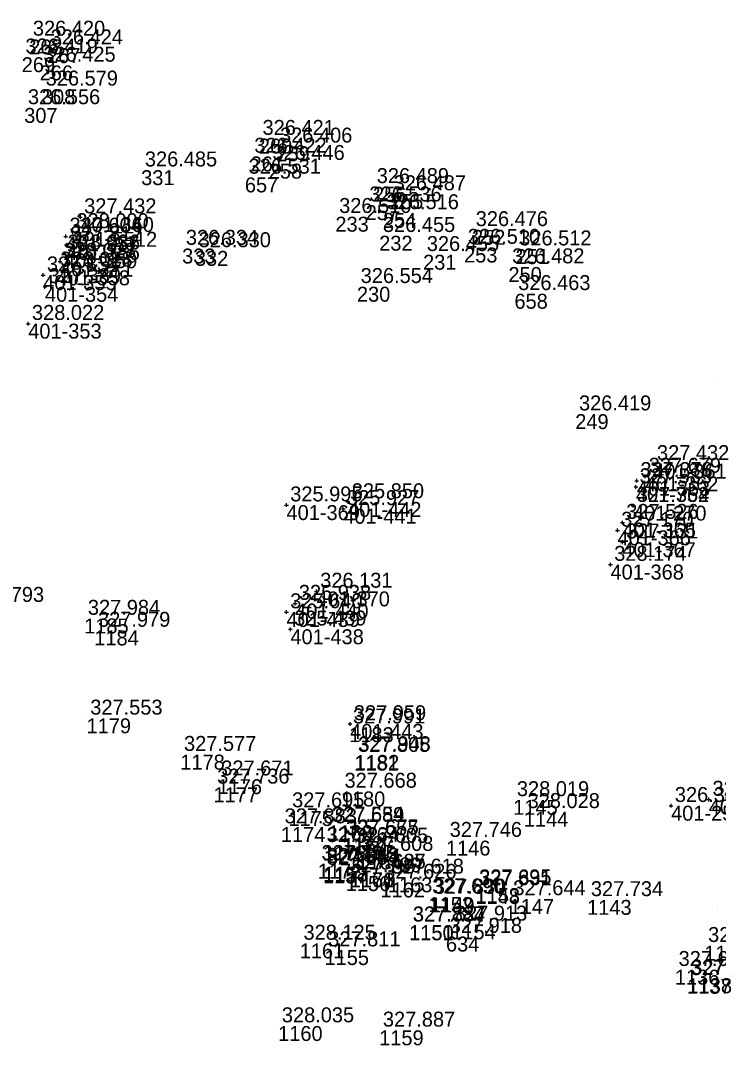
# Model space of a CAD drawing. Extents: x -829398 to -819400, y -1074439 to -1067977.
# Drawn here: x -824002.7 to -823946.7, y -1070110.4 to -1070028 of the extents above; entities that cross this region are included whole.
import ezdxf

# ---------------------------------------------------------------- set-up
doc = ezdxf.new("R2010")
doc.units = 0
for name, color, linetype in [('Vrstva 60', 7, 'Continuous'), ('Vrstva 61', 7, 'Continuous'), ('Čísla bodů_doměření_2012', 7, 'Continuous')]:
    doc.layers.add(name, color=color, linetype=linetype)

# ---------------------------------------------------------------- blocks, each defined once
blk = doc.blocks.new('BOD')
at = {"layer": 'Čísla bodů_doměření_2012'}
for p, q in [((-0.15, 0), (0.15, 0)), ((0, -0.15), (0, 0.15))]:
    blk.add_line(p, q, dxfattribs=at)

msp = doc.modelspace()

# ---------------------------------------------------------------- linework, layer by layer
at = {"layer": 'Vrstva 60'}
for p, q in [((-824002.029, -1070029.543), (-824002.029, -1070029.543)), ((-824000.6, -1070030.246), (-824000.6, -1070030.246)), ((-824002.627, -1070030.975), (-824002.627, -1070030.975)), ((-824001.187, -1070031.632), (-824001.187, -1070031.632)), ((-824001.003, -1070033.552), (-824001.003, -1070033.552)), ((-824002.426, -1070035.05), (-824002.426, -1070035.05)), ((-823983.597, -1070037.514), (-823983.597, -1070037.514)), ((-823982.191, -1070038.132), (-823982.191, -1070038.132)), ((-823984.253, -1070038.949), (-823984.253, -1070038.949)), ((-823993.039, -1070040.049), (-823993.039, -1070040.049)), ((-823982.8, -1070039.527), (-823982.8, -1070039.527)), ((-823984.715, -1070040.629), (-823984.715, -1070040.629)), ((-823974.431, -1070041.383), (-823974.431, -1070041.383)), ((-823973.068, -1070041.962), (-823973.068, -1070041.962)), ((-823975.02, -1070042.857), (-823975.02, -1070042.857)), ((-823973.636, -1070043.483), (-823973.636, -1070043.483)), ((-823977.448, -1070043.786), (-823977.448, -1070043.786)), ((-823966.486, -1070044.842), (-823966.486, -1070044.842)), ((-823973.933, -1070045.313), (-823973.933, -1070045.313)), ((-823989.751, -1070046.345), (-823989.751, -1070046.345)), ((-823988.726, -1070046.533), (-823988.726, -1070046.533)), ((-823967.119, -1070046.264), (-823967.119, -1070046.264)), ((-823962.994, -1070046.391), (-823962.994, -1070046.391)), ((-823970.411, -1070046.841), (-823970.411, -1070046.841)), ((-823963.56, -1070047.83), (-823963.56, -1070047.83)), ((-823975.72, -1070049.412), (-823975.72, -1070049.412)), ((-823963.078, -1070049.979), (-823963.078, -1070049.979)), ((-823946.778, -1070056.953), (-823946.778, -1070056.953)), ((-823958.196, -1070059.645), (-823958.196, -1070059.645)), ((-823997.615, -1070076.062), (-823997.615, -1070076.062)), ((-823996.8, -1070077.023), (-823996.8, -1070077.023)), ((-823997.423, -1070084.082), (-823997.423, -1070084.082)), ((-823976.34, -1070084.793), (-823976.34, -1070084.793)), ((-823989.897, -1070086.997), (-823989.897, -1070086.997)), ((-823975.933, -1070087.077), (-823975.933, -1070087.077)), ((-823975.893, -1070087.022), (-823975.893, -1070087.022)), ((-823987.234, -1070089.622), (-823987.234, -1070089.622)), ((-823986.911, -1070088.967), (-823986.911, -1070088.967)), ((-823977.014, -1070089.956), (-823977.014, -1070089.956)), ((-823963.181, -1070090.63), (-823963.181, -1070090.63)), ((-823981.224, -1070091.527), (-823981.224, -1070091.527)), ((-823962.322, -1070091.59), (-823962.322, -1070091.59)), ((-823981.823, -1070092.814), (-823981.823, -1070092.814)), ((-823978.022, -1070092.709), (-823978.022, -1070092.709)), ((-823978.019, -1070092.663), (-823978.019, -1070092.663)), ((-823976.859, -1070093.703), (-823976.859, -1070093.703)), ((-823978.453, -1070094.318), (-823978.453, -1070094.318)), ((-823976.896, -1070093.766), (-823976.896, -1070093.766)), ((-823976.1, -1070094.371), (-823976.1, -1070094.371)), ((-823968.575, -1070093.905), (-823968.575, -1070093.905)), ((-823975.685, -1070095.028), (-823975.685, -1070095.028)), ((-823978.864, -1070095.76), (-823978.864, -1070095.76)), ((-823978.443, -1070096.139), (-823978.443, -1070096.139)), ((-823978.421, -1070095.997), (-823978.421, -1070095.997)), ((-823976.617, -1070096.756), (-823976.617, -1070096.756)), ((-823976.312, -1070096.457), (-823976.312, -1070096.457)), ((-823976.298, -1070096.46), (-823976.298, -1070096.46)), ((-823973.238, -1070096.854), (-823973.238, -1070096.854)), ((-823973.834, -1070097.265), (-823973.834, -1070097.265)), ((-823966.207, -1070097.716), (-823966.207, -1070097.716)), ((-823966.204, -1070097.784), (-823966.204, -1070097.784)), ((-823969.978, -1070098.442), (-823969.978, -1070098.442)), ((-823969.848, -1070098.475), (-823969.848, -1070098.475)), ((-823963.463, -1070098.588), (-823963.463, -1070098.588)), ((-823957.244, -1070098.663), (-823957.244, -1070098.663)), ((-823946.782, -1070099.418), (-823946.782, -1070099.418)), ((-823946.753, -1070099.384), (-823946.753, -1070099.384)), ((-823971.538, -1070100.71), (-823971.538, -1070100.71)), ((-823971.524, -1070100.69), (-823971.524, -1070100.69)), ((-823968.152, -1070100.629), (-823968.152, -1070100.629)), ((-823968.573, -1070101.612), (-823968.573, -1070101.612)), ((-823980.311, -1070102.162), (-823980.311, -1070102.162)), ((-823978.323, -1070102.695), (-823978.323, -1070102.695)), ((-823947.833, -1070102.345), (-823947.833, -1070102.345)), ((-823950.202, -1070104.272), (-823950.202, -1070104.272)), ((-823949.233, -1070105.007), (-823949.233, -1070105.007)), ((-823949.183, -1070104.954), (-823949.183, -1070104.954)), ((-823982.045, -1070108.797), (-823982.045, -1070108.797)), ((-823973.935, -1070109.143), (-823973.935, -1070109.143))]:
    msp.add_line(p, q, dxfattribs=at)

# ---------------------------------------------------------------- block references
for p in [(-823997.913, -1070043.812), (-823998.536, -1070045.004), (-823999.091, -1070045.366), (-823999.032, -1070046.05), (-823999.232, -1070046.723), (-823999.549, -1070047.392), (-824000.903, -1070048.477), (-823999.825, -1070048.096), (-824000.761, -1070049.42), (-824002.102, -1070052.378), (-823951.937, -1070063.636), (-823953.263, -1070064.996), (-823952.598, -1070064.648), (-823953.33, -1070065.497), (-823976.432, -1070066.702), (-823981.373, -1070066.953), (-823976.817, -1070067.251), (-823953.557, -1070066.997), (-823954.403, -1070068.359), (-823954.806, -1070068.984), (-823954.412, -1070069.931), (-823955.369, -1070071.728), (-823978.967, -1070073.886), (-823980.68, -1070074.863), (-823981.374, -1070075.541), (-823981.058, -1070076.925), (-823976.266, -1070084.532), (-823947.481, -1070090.598), (-823950.502, -1070091.099)]:
    msp.add_blockref('BOD', p, dxfattribs=at)

# ---------------------------------------------------------------- texts
for s, p in [('268', (-824002.029, -1070030.743)), ('267', (-824000.6, -1070031.446)), ('269', (-824002.627, -1070032.175)), ('266', (-824001.187, -1070032.832)), ('308', (-824001.003, -1070034.752)), ('307', (-824002.426, -1070036.25)), ('260', (-823983.597, -1070038.714)), ('259', (-823982.191, -1070039.332)), ('261', (-823984.253, -1070040.149)), ('331', (-823993.039, -1070041.249)), ('258', (-823982.8, -1070040.727)), ('657', (-823984.715, -1070041.829)), ('256', (-823974.431, -1070042.583)), ('255', (-823973.068, -1070043.162)), ('257', (-823975.02, -1070044.057)), ('254', (-823973.636, -1070044.683)), ('401-360', (-823997.913, -1070045.012)), ('233', (-823977.448, -1070044.986)), ('401-5512', (-823998.536, -1070046.204)), ('252', (-823966.486, -1070046.042)), ('401-357', (-823999.091, -1070046.566)), ('232', (-823973.933, -1070046.513)), ('401-359', (-823999.232, -1070047.923)), ('401-356', (-823999.032, -1070047.25)), ('333', (-823989.751, -1070047.545)), ('332', (-823988.726, -1070047.733)), ('231', (-823970.411, -1070048.041)), ('253', (-823967.119, -1070047.464)), ('251', (-823962.994, -1070047.591)), ('401-271', (-823999.549, -1070048.592)), ('401-355', (-824000.903, -1070049.677)), ('401-358', (-823999.825, -1070049.296)), ('250', (-823963.56, -1070049.03)), ('401-354', (-824000.761, -1070050.62)), ('230', (-823975.72, -1070050.612)), ('658', (-823963.078, -1070051.179)), ('401-353', (-824002.102, -1070053.578)), ('249', (-823958.196, -1070060.845)), ('401-361', (-823951.937, -1070064.836)), ('401-362', (-823952.598, -1070065.848)), ('401-364', (-823953.33, -1070066.697)), ('401-363', (-823953.263, -1070066.196)), ('401-369', (-823981.373, -1070068.153)), ('401-441', (-823976.817, -1070068.451)), ('401-442', (-823976.432, -1070067.902)), ('401-270', (-823953.557, -1070068.197)), ('401-366', (-823954.806, -1070070.184)), ('401-365', (-823954.403, -1070069.559)), ('401-367', (-823954.412, -1070071.131)), ('401-368', (-823955.369, -1070072.928)), ('401-370', (-823978.967, -1070075.086)), ('401-439', (-823981.374, -1070076.741)), ('401-440', (-823980.68, -1070076.063)), ('1185', (-823997.615, -1070077.262)), ('1184', (-823996.8, -1070078.223)), ('401-438', (-823981.058, -1070078.125)), ('1179', (-823997.423, -1070085.282)), ('401-443', (-823976.266, -1070085.732)), ('1183', (-823976.34, -1070085.993)), ('1178', (-823989.897, -1070088.197)), ('1181', (-823975.933, -1070088.277)), ('1182', (-823975.893, -1070088.222)), ('1177', (-823987.234, -1070090.822)), ('1176', (-823986.911, -1070090.167)), ('1180', (-823977.014, -1070091.156)), ('1145', (-823963.181, -1070091.83)), ('401-259', (-823950.502, -1070092.299)), ('401-258', (-823947.481, -1070091.798)), ('1175', (-823981.224, -1070092.727)), ('1144', (-823962.322, -1070092.79)), ('1174', (-823981.823, -1070094.014)), ('1169', (-823978.022, -1070093.909)), ('1168', (-823978.019, -1070093.863)), ('1170', (-823976.896, -1070094.966)), ('1167', (-823976.859, -1070094.903)), ('1173', (-823978.453, -1070095.518)), ('1165', (-823976.1, -1070095.571)), ('1146', (-823968.575, -1070095.105)), ('1164', (-823975.685, -1070096.228)), ('1172', (-823978.864, -1070096.96)), ('1157', (-823978.443, -1070097.339)), ('1158', (-823978.421, -1070097.197)), ('1156', (-823976.617, -1070097.956)), ('1166', (-823976.312, -1070097.657)), ('1171', (-823976.298, -1070097.66)), ('1163', (-823973.238, -1070098.054)), ('1162', (-823973.834, -1070098.465)), ('1153', (-823966.207, -1070098.916)), ('1148', (-823966.204, -1070098.984)), ('1152', (-823969.978, -1070099.642)), ('1149', (-823969.848, -1070099.675)), ('1147', (-823963.463, -1070099.788)), ('1143', (-823957.244, -1070099.863)), ('1151', (-823971.538, -1070101.91)), ('1150', (-823971.524, -1070101.89)), ('1154', (-823968.152, -1070101.829)), ('634', (-823968.573, -1070102.812)), ('1161', (-823980.311, -1070103.362)), ('1155', (-823978.323, -1070103.895)), ('1139', (-823947.833, -1070103.545)), ('1136', (-823950.202, -1070105.472)), ('1137', (-823949.233, -1070106.207)), ('1138', (-823949.183, -1070106.154)), ('1160', (-823982.045, -1070109.997)), ('1159', (-823973.935, -1070110.343))]:
    msp.add_text(s, height=1.2, dxfattribs=at).set_placement(p)
at = {"layer": 'Vrstva 61'}
for s, p in [('326.420', (-824001.729, -1070029.243)), ('326.419', (-824002.327, -1070030.675)), ('326.424', (-824000.3, -1070029.946)), ('326.425', (-824000.887, -1070031.332)), ('326.579', (-824000.703, -1070033.252)), ('326.556', (-824002.126, -1070034.75)), ('326.421', (-823983.297, -1070037.214)), ('326.406', (-823981.891, -1070037.832)), ('326.422', (-823983.953, -1070038.649)), ('326.485', (-823992.739, -1070039.749)), ('326.446', (-823982.5, -1070039.227)), ('326.531', (-823984.415, -1070040.329)), ('326.489', (-823974.131, -1070041.083)), ('326.487', (-823972.768, -1070041.662)), ('326.536', (-823974.72, -1070042.557)), ('327.432', (-823997.613, -1070043.512)), ('326.510', (-823977.148, -1070043.486)), ('326.516', (-823973.336, -1070043.183)), ('328.000', (-823998.236, -1070044.704)), ('326.476', (-823966.186, -1070044.542)), ('327.604', (-823998.791, -1070045.066)), ('326.455', (-823973.633, -1070045.013)), ('327.812', (-823998.732, -1070045.75)), ('326.334', (-823989.451, -1070046.045)), ('326.330', (-823988.426, -1070046.233)), ('326.510', (-823966.819, -1070045.964)), ('326.512', (-823962.694, -1070046.091)), ('328.028', (-823999.249, -1070047.092)), ('328.036', (-823998.932, -1070046.423)), ('326.455', (-823970.111, -1070046.541)), ('328.028', (-823999.525, -1070047.796)), ('326.482', (-823963.26, -1070047.53)), ('327.834', (-824000.603, -1070048.177)), ('327.389', (-824000.461, -1070049.12)), ('326.554', (-823975.42, -1070049.112)), ('326.463', (-823962.778, -1070049.679)), ('328.022', (-824001.802, -1070052.078)), ('326.419', (-823957.896, -1070059.345)), ('327.432', (-823951.637, -1070063.336)), ('327.679', (-823952.298, -1070064.348)), ('327.583', (-823953.03, -1070065.197)), ('327.378', (-823952.963, -1070064.696)), ('325.995', (-823981.073, -1070066.653)), ('325.927', (-823976.517, -1070066.951)), ('325.850', (-823976.132, -1070066.402)), ('327.752', (-823953.257, -1070066.697)), ('327.526', (-823954.103, -1070068.059)), ('327.170', (-823954.506, -1070068.684)), ('327.131', (-823954.112, -1070069.631)), ('328.174', (-823955.069, -1070071.428)), ('326.131', (-823978.667, -1070073.586)), ('327.793', (-824006.629, -1070074.727)), ('325.938', (-823980.38, -1070074.563)), ('327.984', (-823997.315, -1070075.762)), ('325.640', (-823981.074, -1070075.241)), ('327.979', (-823996.5, -1070076.723)), ('325.439', (-823980.758, -1070076.625)), ('327.553', (-823997.123, -1070083.782)), ('327.959', (-823975.966, -1070084.232)), ('327.991', (-823976.04, -1070084.493)), ('327.577', (-823989.597, -1070086.697)), ('327.948', (-823975.593, -1070086.722)), ('327.805', (-823975.633, -1070086.777)), ('327.671', (-823986.611, -1070088.667)), ('327.736', (-823986.934, -1070089.322)), ('327.668', (-823976.714, -1070089.656)), ('328.019', (-823962.881, -1070090.33)), ('326.343', (-823950.202, -1070090.799)), ('325.780', (-823947.181, -1070090.298)), ('327.695', (-823980.924, -1070091.227)), ('328.028', (-823962.022, -1070091.29)), ('327.689', (-823977.722, -1070092.409)), ('327.554', (-823977.719, -1070092.363)), ('327.883', (-823981.523, -1070092.514)), ('327.764', (-823978.153, -1070094.018)), ('327.657', (-823976.596, -1070093.466)), ('327.575', (-823976.559, -1070093.403)), ('327.605', (-823975.8, -1070094.071)), ('327.746', (-823968.275, -1070093.605)), ('327.608', (-823975.385, -1070094.728)), ('327.797', (-823978.564, -1070095.46)), ('327.848', (-823978.121, -1070095.697)), ('327.854', (-823978.143, -1070095.839)), ('327.789', (-823976.317, -1070096.456)), ('327.627', (-823976.012, -1070096.157)), ('327.685', (-823975.998, -1070096.16)), ('327.618', (-823972.938, -1070096.554)), ('327.626', (-823973.534, -1070096.965)), ('327.695', (-823965.907, -1070097.416)), ('327.690', (-823969.678, -1070098.142)), ('327.830', (-823969.548, -1070098.175)), ('327.831', (-823965.904, -1070097.484)), ('327.644', (-823963.163, -1070098.288)), ('327.734', (-823956.944, -1070098.363)), ('327.734', (-823971.238, -1070100.41)), ('327.887', (-823971.224, -1070100.39)), ('327.913', (-823967.852, -1070100.329)), ('327.918', (-823968.273, -1070101.312)), ('328.125', (-823980.011, -1070101.862)), ('327.772', (-823947.533, -1070102.045)), ('327.811', (-823978.023, -1070102.395)), ('327.668', (-823949.902, -1070103.972)), ('327.830', (-823948.933, -1070104.707)), ('327.692', (-823948.883, -1070104.654)), ('328.035', (-823981.745, -1070108.497)), ('327.887', (-823973.635, -1070108.843))]:
    msp.add_text(s, height=1.2, dxfattribs=at).set_placement(p)

doc.saveas('drawing.dxf')
